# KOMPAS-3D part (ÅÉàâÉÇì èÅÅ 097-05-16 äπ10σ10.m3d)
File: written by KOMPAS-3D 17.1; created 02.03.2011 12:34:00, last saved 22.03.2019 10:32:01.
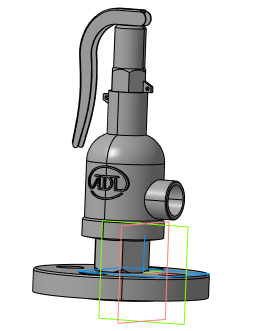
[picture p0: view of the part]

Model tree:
1. Плоскость XY
2. Плоскость ZX
3. Плоскость ZY
4. Ось X
5. Ось Y
6. Ось Z
7. Начало координат
8. Операция без истории:2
